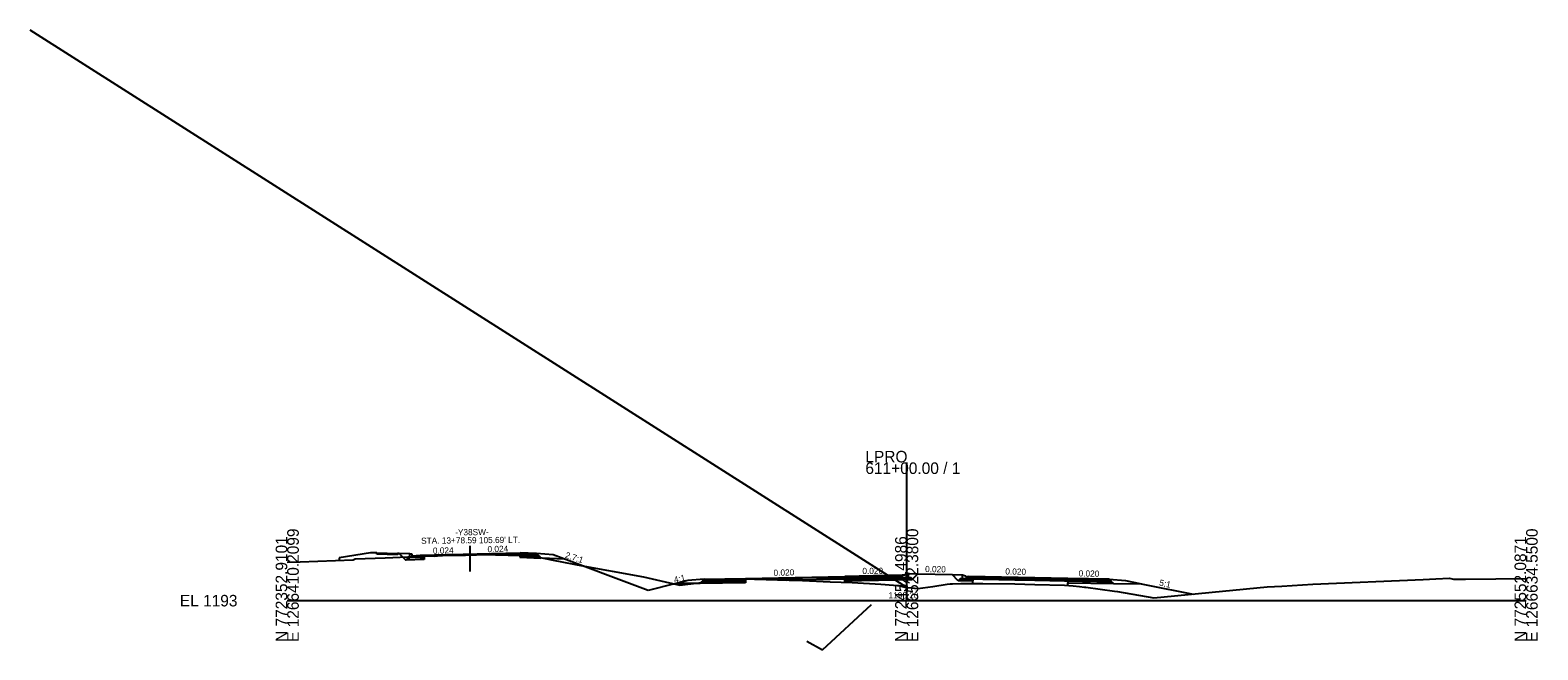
# Model space of a CAD drawing. Extents: x -3833 to 1267678, y -522 to 773248.
# Drawn here: x 1937.8 to 2302.8, y 1988.1 to 2138.3 of the extents above; entities that cross this region are included whole.
import ezdxf

# ---------------------------------------------------------------- set-up
doc = ezdxf.new("R2010")
doc.units = 0
for name, color, linetype in [('Exist Cross Section Cell', 7, 'Continuous'), ('Exist XS Center Line Elevation Label', 7, 'Continuous'), ('Exist XS Ground Line', 7, 'Continuous'), ('Prop CMT DNC', 7, 'Continuous'), ('Prop CMT Pvmt Course 1', 7, 'Continuous'), ('Prop CMT Pvmt Course 2', 7, 'Continuous'), ('Prop CMT Pvmt Course 3', 7, 'Continuous'), ('Prop CMT Pvmt Course 4', 7, 'Continuous'), ('Prop CMT Shld Paved Course 1', 7, 'Continuous'), ('Prop CMT Shld Paved Course 2', 7, 'Continuous'), ('Prop CMT Shld Paved Course 4', 7, 'Continuous'), ('Prop CMT Slope Fill', 7, 'Continuous'), ('Prop CMT Slope Grass', 7, 'Continuous'), ('Prop CMT Subgrade Earthwork', 7, 'Continuous'), ('Prop Conc 4in Sidewalk', 7, 'Continuous'), ('Prop Conc Curb and Gutter', 7, 'Continuous'), ('Prop Conc Island Cover', 7, 'Continuous'), ('Prop Corridor Mesh Bottom', 7, 'Continuous'), ('Prop XS Ditch Slope Text', 7, 'Continuous'), ('Prop XS Finish Grade', 7, 'Continuous'), ('Prop XS SE Text', 7, 'Continuous'), ('Prop XS Shear Point Element', 7, 'Continuous'), ('Prop XS Shear Point Label', 7, 'Continuous'), ('Scratch_Level_1', 7, 'Continuous'), ('Scratch_Level_5', 7, 'Continuous')]:
    doc.layers.add(name, color=color, linetype=linetype)

msp = doc.modelspace()

# ---------------------------------------------------------------- linework, layer by layer
at = {"layer": 'Exist Cross Section Cell'}
for p, q in [((2150, 2000), (2150, 2033.5)), ((2000, 2000), (2150, 2000)), ((2150, 2000), (2300, 2000))]:
    msp.add_line(p, q, dxfattribs=at)
at = {"layer": 'Exist XS Ground Line'}
for p, q in [((2000, 2009.3), (2003.1, 2009.4)), ((2003.1, 2009.4), (2015.97, 2009.92)), ((2015.97, 2009.92), (2016.47, 2010.11)), ((2016.47, 2010.11), (2023.71, 2010.36)), ((2023.71, 2010.36), (2029.18, 2010.6)), ((2029.18, 2010.6), (2037.57, 2010.91)), ((2037.57, 2010.91), (2041.57, 2011.02)), ((2041.57, 2011.02), (2043.16, 2011.06)), ((2043.16, 2011.06), (2044.63, 2011.1)), ((2044.63, 2011.1), (2045.84, 2011.13)), ((2045.84, 2011.13), (2047.34, 2011.17)), ((2047.34, 2011.17), (2056.54, 2010.98)), ((2056.54, 2010.98), (2058.68, 2010.94)), ((2058.68, 2010.94), (2061.64, 2010.35)), ((2061.64, 2010.35), (2064.77, 2009.72)), ((2064.77, 2009.72), (2066.12, 2009.46)), ((2066.12, 2009.46), (2070.19, 2008.72)), ((2070.19, 2008.72), (2086.27, 2005.78)), ((2086.27, 2005.78), (2091.54, 2004.53)), ((2091.54, 2004.53), (2095.06, 2003.75)), ((2099.06, 2004.26), (2104.76, 2004.93)), ((2104.76, 2004.93), (2106.62, 2005.16)), ((2106.62, 2005.16), (2107.61, 2005.27)), ((2107.61, 2005.27), (2109.06, 2005.26)), ((2109.06, 2005.26), (2113.22, 2005.24)), ((2113.22, 2005.24), (2121.55, 2004.98)), ((2121.55, 2004.98), (2124.8, 2004.88)), ((2124.8, 2004.88), (2131.44, 2004.6)), ((2131.44, 2004.6), (2136.83, 2004.39)), ((2136.83, 2004.39), (2143.74, 2003.97)), ((2248.36, 2003.97), (2275.09, 2005.13)), ((2275.09, 2005.13), (2278.17, 2005.26)), ((2278.17, 2005.26), (2281.47, 2005.43)), ((2281.47, 2005.43), (2282.42, 2005.19)), ((2282.42, 2005.19), (2285.33, 2005.22)), ((2285.33, 2005.22), (2300, 2005.38)), ((2095.06, 2003.75), (2099.06, 2004.26)), ((2143.74, 2003.97), (2146.81, 2003.79)), ((2146.81, 2003.79), (2147.75, 2003.71)), ((2147.75, 2003.71), (2148.12, 2003.68)), ((2148.12, 2003.68), (2149.61, 2003.24)), ((2149.61, 2003.24), (2150, 2003.2)), ((2150, 2003.2), (2151.12, 2003.09)), ((2151.12, 2003.09), (2152.67, 2002.94)), ((2152.67, 2002.94), (2156.36, 2003.42)), ((2156.36, 2003.42), (2159.79, 2003.98)), ((2159.79, 2003.98), (2160.57, 2004.06)), ((2160.57, 2004.06), (2161.11, 2004.1)), ((2161.11, 2004.1), (2163.11, 2004.15)), ((2163.11, 2004.15), (2164.19, 2004.16)), ((2164.19, 2004.16), (2168.46, 2004.14)), ((2168.46, 2004.14), (2176.23, 2004.1)), ((2176.23, 2004.1), (2181, 2003.95)), ((2181, 2003.95), (2188.25, 2003.73)), ((2188.25, 2003.73), (2190.31, 2003.56)), ((2190.31, 2003.56), (2191.82, 2003.45)), ((2191.82, 2003.45), (2193.04, 2003.29)), ((2193.04, 2003.29), (2193.39, 2003.24)), ((2193.39, 2003.24), (2200.33, 2002.31)), ((2200.33, 2002.31), (2201.07, 2002.18)), ((2201.07, 2002.18), (2209.89, 2000.65)), ((2209.89, 2000.65), (2237.32, 2003.35)), ((2237.32, 2003.35), (2240.81, 2003.51)), ((2240.81, 2003.51), (2248.36, 2003.97))]:
    msp.add_line(p, q, dxfattribs=at)
at = {"layer": 'Prop CMT Pvmt Course 1'}
for p, q in [((2029.2, 2010.33), (2029.68, 2010.34)), ((2032.18, 2011.01), (2056.37, 2011.59)), ((2032.18, 2010.76), (2036.4, 2010.86)), ((2032.18, 2010.43), (2033.18, 2010.45)), ((2048.22, 2011.15), (2056.37, 2011.34)), ((2055.79, 2011), (2056.36, 2011.01)), ((2111, 2005.38), (2135, 2005.86)), ((2135, 2005.61), (2111, 2005.25)), ((2111, 2005.25), (2111, 2005.38)), ((2111, 2005.38), (2111, 2005.38)), ((2135, 2005.86), (2135, 2005.86)), ((2135, 2005.86), (2135, 2005.86)), ((2135, 2005.86), (2135, 2005.61)), ((2135, 2005.61), (2135, 2005.61)), ((2189, 2005.38), (2165, 2005.86)), ((2165, 2005.86), (2165, 2005.86)), ((2165, 2005.86), (2165, 2005.86)), ((2165, 2005.86), (2165, 2005.61)), ((2165, 2005.61), (2165, 2005.61)), ((2189, 2005.13), (2189, 2005.38)), ((2189, 2005.38), (2189, 2005.38))]:
    msp.add_line(p, q, dxfattribs=at)
at = {"layer": 'Prop CMT Pvmt Course 2'}
for p, q in [((2148.91, 2005.89), (2135, 2005.61)), ((2135, 2005.61), (2135, 2005.61)), ((2135, 2005.61), (2135, 2005.28)), ((2135, 2005.28), (2148.91, 2005.56)), ((2135, 2005.28), (2135, 2005.28)), ((2150, 2005.58), (2150, 2005.58)), ((2150, 2005.58), (2150, 2005.58)), ((2165, 2005.28), (2165, 2005.61)), ((2165, 2005.61), (2165, 2005.61)), ((2165, 2005.28), (2165, 2005.28))]:
    msp.add_line(p, q, dxfattribs=at)
at = {"layer": 'Prop CMT Pvmt Course 3'}
for p, q in [((2148.92, 2005.56), (2148.91, 2005.56)), ((2150.92, 2005.6), (2148.92, 2005.56)), ((2151.21, 2005.31), (2150.92, 2005.6)), ((2162.7, 2005.03), (2162.99, 2005.32)), ((2166, 2005.84), (2166, 2004.77))]:
    msp.add_line(p, q, dxfattribs=at)
at = {"layer": 'Prop CMT Pvmt Course 4'}
for p, q in [((2028.7, 2009.85), (2029.2, 2010.33)), ((2028.7, 2009.85), (2028.7, 2009.85)), ((2028.7, 2009.85), (2028.7, 2009.85)), ((2032.18, 2009.97), (2032.18, 2009.97)), ((2135, 2005.28), (2148.91, 2005.56)), ((2135, 2004.46), (2135, 2005.28)), ((2135, 2005.28), (2135, 2005.28)), ((2135, 2005.28), (2135, 2005.28)), ((2135, 2004.82), (2151.37, 2005.15)), ((2150, 2005.58), (2150, 2005.58)), ((2150, 2005.58), (2150, 2005.58)), ((2150.42, 2005.59), (2150.92, 2005.6)), ((2150.92, 2005.6), (2151.37, 2005.15)), ((2162.99, 2005.32), (2162.51, 2004.84)), ((2163.49, 2005.31), (2162.99, 2005.32)), ((2165, 2005.28), (2165, 2005.28)), ((2165, 2005.28), (2165, 2005.28))]:
    msp.add_line(p, q, dxfattribs=at)
at = {"layer": 'Prop CMT Shld Paved Course 1'}
for p, q in [((2032.18, 2010.43), (2032.18, 2010.43)), ((2035.66, 2011), (2035.66, 2011)), ((2035.66, 2010.52), (2035.66, 2010.52)), ((2041.45, 2011.2), (2041.45, 2011.2)), ((2041.45, 2010.9), (2041.45, 2010.9)), ((2044.3, 2011.3), (2044.3, 2011.3)), ((2044.3, 2011.06), (2044.3, 2011.06)), ((2044.3, 2011.06), (2044.3, 2011.06)), ((2044.3, 2011.06), (2044.3, 2011.06)), ((2044.63, 2011.32), (2044.63, 2011.32)), ((2044.63, 2011.07), (2044.63, 2011.07)), ((2045.05, 2011.1), (2045.05, 2011.1)), ((2045.06, 2011.33), (2045.06, 2011.33)), ((2047.64, 2011.42), (2047.64, 2011.42)), ((2047.64, 2011.19), (2047.64, 2011.19)), ((2047.87, 2011.2), (2047.87, 2011.2)), ((2047.87, 2011.2), (2047.87, 2011.2)), ((2047.88, 2011.43), (2047.88, 2011.43)), ((2047.88, 2011.43), (2047.88, 2011.43)), ((2050.06, 2011.51), (2050.06, 2011.51)), ((2050.06, 2011.21), (2050.06, 2011.21)), ((2056.37, 2011.59), (2056.36, 2011.09)), ((2056.36, 2011.09), (2056.36, 2011.09)), ((2060.37, 2011.41), (2056.37, 2011.59)), ((2056.37, 2011.59), (2056.37, 2011.34)), ((2056.37, 2011.34), (2056.37, 2011.34)), ((2056.37, 2011.34), (2060.63, 2011.15)), ((2060.63, 2011.15), (2060.37, 2011.41)), ((2060.37, 2011.41), (2060.37, 2011.41)), ((2060.63, 2011.15), (2060.63, 2011.15)), ((2060.63, 2011.15), (2060.63, 2011.15)), ((2100.74, 2004.93), (2101, 2005.18)), ((2111, 2005.13), (2100.74, 2004.93)), ((2101, 2005.18), (2111, 2005.38)), ((2111, 2005.38), (2111, 2005.13)), ((2148.91, 2006.14), (2135, 2005.86)), ((2135, 2005.61), (2148.91, 2005.89)), ((2135, 2005.86), (2135, 2005.86)), ((2135, 2005.86), (2135, 2005.61)), ((2150, 2006.16), (2150, 2006.16)), ((2150, 2006.16), (2150, 2006.16)), ((2150, 2005.91), (2150, 2005.91)), ((2165, 2005.61), (2165, 2005.86)), ((2165, 2005.86), (2165, 2005.86)), ((2189, 2005.38), (2189, 2005.13)), ((2199, 2005.18), (2189, 2005.38)), ((2189, 2005.13), (2199.26, 2004.93)), ((2199.26, 2004.93), (2199, 2005.18))]:
    msp.add_line(p, q, dxfattribs=at)
at = {"layer": 'Prop CMT Shld Paved Course 2'}
for p, q in [((2032.18, 2010.43), (2032.18, 2010.43)), ((2033.18, 2010.46), (2033.18, 2010.46)), ((2033.18, 2010.46), (2033.18, 2010.46)), ((2056.37, 2011.34), (2056.36, 2011.01)), ((2056.36, 2011.01), (2056.36, 2011.01)), ((2056.36, 2011.01), (2060.97, 2010.8)), ((2060.63, 2011.15), (2056.37, 2011.34)), ((2060.97, 2010.8), (2060.63, 2011.15)), ((2060.63, 2011.15), (2060.63, 2011.15)), ((2060.97, 2010.8), (2060.97, 2010.8)), ((2060.97, 2010.8), (2060.97, 2010.8)), ((2100.41, 2004.59), (2100.74, 2004.93)), ((2111, 2004.8), (2100.41, 2004.59)), ((2100.74, 2004.93), (2111, 2005.13)), ((2111, 2005.13), (2111, 2004.8)), ((2111.01, 2005.25), (2113.17, 2005.24)), ((2113.17, 2005.24), (2111.01, 2005.25)), ((2113.17, 2005.24), (2113.23, 2005.24)), ((2113.3, 2005.24), (2113.17, 2005.24)), ((2113.23, 2005.24), (2113.3, 2005.24)), ((2121.55, 2005.34), (2113.3, 2005.24)), ((2113.3, 2005.24), (2114.43, 2005.2)), ((2114.43, 2005.2), (2114.43, 2005.2)), ((2114.43, 2005.2), (2120.94, 2005)), ((2120.94, 2005), (2121.55, 2005.01)), ((2120.94, 2005), (2120.94, 2005)), ((2124.8, 2005.41), (2121.55, 2005.34)), ((2121.55, 2005.34), (2121.55, 2005.34)), ((2121.55, 2005.01), (2124.8, 2005.07)), ((2121.55, 2005.01), (2121.55, 2005.01)), ((2131.44, 2005.54), (2124.8, 2005.41)), ((2124.8, 2005.07), (2131.44, 2005.21)), ((2135, 2005.61), (2131.44, 2005.54)), ((2131.44, 2005.54), (2131.44, 2005.54)), ((2131.44, 2005.21), (2135, 2005.28)), ((2131.44, 2005.21), (2131.44, 2005.21)), ((2135, 2005.28), (2135, 2005.61)), ((2135, 2005.61), (2135, 2005.61)), ((2135, 2005.61), (2135, 2005.61)), ((2135, 2005.28), (2135, 2005.28)), ((2168.46, 2005.54), (2165, 2005.61)), ((2165, 2005.61), (2165, 2005.61)), ((2165, 2005.61), (2165, 2005.28)), ((2165, 2005.28), (2168.46, 2005.21)), ((2176.23, 2005.39), (2168.46, 2005.54)), ((2168.46, 2005.54), (2168.46, 2005.54)), ((2168.46, 2005.21), (2168.46, 2005.21)), ((2168.46, 2005.21), (2176.23, 2005.05)), ((2181, 2005.29), (2176.23, 2005.39)), ((2176.23, 2005.39), (2176.23, 2005.39)), ((2176.23, 2005.05), (2176.23, 2005.05)), ((2176.23, 2005.05), (2181, 2004.96)), ((2188.25, 2005.15), (2181, 2005.29)), ((2181, 2005.29), (2181, 2005.29)), ((2181, 2004.96), (2181, 2004.96)), ((2181, 2004.96), (2188.25, 2004.81)), ((2188.25, 2005.15), (2188.25, 2005.15)), ((2189, 2005.13), (2188.25, 2005.15)), ((2188.25, 2005.15), (2188.25, 2005.15)), ((2188.25, 2004.81), (2188.25, 2004.81)), ((2188.25, 2004.81), (2188.25, 2004.81)), ((2188.25, 2004.81), (2189, 2004.8)), ((2189, 2004.8), (2189, 2005.13)), ((2189, 2005.13), (2189, 2005.13)), ((2189, 2005.13), (2189, 2004.8)), ((2199.26, 2004.93), (2189, 2005.13)), ((2189, 2004.8), (2199.59, 2004.59)), ((2199.59, 2004.59), (2199.26, 2004.93))]:
    msp.add_line(p, q, dxfattribs=at)
at = {"layer": 'Prop CMT Shld Paved Course 4'}
for p, q in [((2032.18, 2009.97), (2032.18, 2009.97)), ((2033.18, 2010.46), (2033.18, 2010.46)), ((2033.18, 2010.01), (2033.18, 2010.01)), ((2033.18, 2010.01), (2033.18, 2010.01)), ((2056.36, 2011.01), (2056.35, 2010.55)), ((2056.35, 2010.55), (2056.35, 2010.55)), ((2056.35, 2010.55), (2061.44, 2010.32)), ((2060.47, 2010.83), (2056.36, 2011.01)), ((2060.97, 2010.8), (2060.47, 2010.83)), ((2060.47, 2010.83), (2060.47, 2010.83)), ((2061.44, 2010.32), (2060.97, 2010.8)), ((2060.97, 2010.8), (2060.97, 2010.8)), ((2061.44, 2010.32), (2061.44, 2010.32)), ((2061.44, 2010.32), (2061.44, 2010.32)), ((2099.94, 2004.12), (2100.41, 2004.59)), ((2111, 2004.34), (2099.94, 2004.12)), ((2100.41, 2004.59), (2100.91, 2004.6)), ((2100.91, 2004.6), (2111, 2004.8)), ((2111, 2004.8), (2111, 2004.34)), ((2189, 2004.8), (2189, 2004.34)), ((2199.09, 2004.6), (2189, 2004.8)), ((2189, 2004.34), (2200.06, 2004.12)), ((2199.59, 2004.59), (2199.09, 2004.6)), ((2200.06, 2004.12), (2199.59, 2004.59))]:
    msp.add_line(p, q, dxfattribs=at)
at = {"layer": 'Prop CMT Slope Grass'}
for p, q in [((2029.68, 2011.37), (2027.1, 2011.43)), ((2064.37, 2011.07), (2060.37, 2011.41)), ((2101, 2005.18), (2097, 2004.86)), ((2150.42, 2006.57), (2150.72, 2006.56)), ((2150.72, 2006.56), (2152.74, 2006.52)), ((2161.01, 2006.34), (2163.49, 2006.29)), ((2199, 2005.18), (2203, 2004.86)), ((2203, 2004.86), (2206.78, 2004.1))]:
    msp.add_line(p, q, dxfattribs=at)
at = {"layer": 'Prop CMT Subgrade Earthwork'}
for p, q in [((2027.1, 2011.43), (2028.7, 2009.85)), ((2033.18, 2010.01), (2028.7, 2009.85)), ((2033.18, 2010.75), (2033.18, 2010.01)), ((2056.36, 2010.98), (2056.35, 2010.55)), ((2067.05, 2010.07), (2056.35, 2010.55)), ((2111, 2004.34), (2099.94, 2004.12)), ((2111, 2005.25), (2111, 2004.34)), ((2151.37, 2005.15), (2135, 2004.82)), ((2135, 2004.82), (2135, 2004.46)), ((2151.37, 2005.15), (2152.74, 2006.52)), ((2162.51, 2004.84), (2161.01, 2006.34)), ((2166, 2004.77), (2162.51, 2004.84)), ((2166, 2004.15), (2166, 2004.77)), ((2189, 2003.66), (2189, 2004.34)), ((2189, 2004.34), (2200.06, 2004.12)), ((2099.94, 2004.12), (2094.3, 2004.19)), ((2200.06, 2004.12), (2206.78, 2004.1))]:
    msp.add_line(p, q, dxfattribs=at)
at = {"layer": 'Prop Conc 4in Sidewalk'}
for p, q in [((2021.67, 2011.23), (2021.68, 2011.57)), ((2026.69, 2011.11), (2021.67, 2011.23)), ((2021.68, 2011.57), (2026.68, 2011.44)), ((2026.68, 2011.44), (2026.69, 2011.11))]:
    msp.add_line(p, q, dxfattribs=at)
at = {"layer": 'Prop Conc Curb and Gutter'}
for p, q in [((2029.68, 2010.34), (2029.68, 2011.37)), ((2029.68, 2011.37), (2029.68, 2011.37)), ((2029.68, 2011.37), (2030.18, 2011.36)), ((2032.18, 2010.43), (2029.68, 2010.34)), ((2029.68, 2010.34), (2029.68, 2010.34)), ((2029.68, 2010.34), (2029.68, 2010.34)), ((2030.18, 2011.36), (2030.18, 2010.86)), ((2030.18, 2010.86), (2032.18, 2011.01)), ((2030.18, 2010.86), (2030.18, 2010.86)), ((2030.18, 2010.86), (2030.18, 2010.86)), ((2032.18, 2011.01), (2032.18, 2010.43)), ((2032.18, 2010.43), (2032.18, 2010.43)), ((2148.91, 2006.14), (2148.91, 2006.14)), ((2148.91, 2006.14), (2148.91, 2005.56)), ((2148.92, 2006.14), (2148.91, 2006.14)), ((2148.91, 2005.56), (2148.92, 2005.56)), ((2149.66, 2006.15), (2148.92, 2006.14)), ((2148.92, 2005.56), (2150.42, 2005.59)), ((2150.42, 2006.57), (2149.66, 2006.32)), ((2149.66, 2006.32), (2149.66, 2006.32)), ((2149.66, 2006.32), (2149.66, 2006.15)), ((2149.66, 2006.15), (2149.66, 2006.15)), ((2150.42, 2005.59), (2150.42, 2006.57)), ((2150.42, 2005.59), (2150.42, 2005.59)), ((2163.49, 2005.31), (2163.49, 2006.29)), ((2163.49, 2006.29), (2163.49, 2006.29)), ((2163.49, 2006.29), (2163.49, 2006.29)), ((2163.49, 2006.29), (2164.25, 2006.04)), ((2165, 2005.28), (2163.49, 2005.31)), ((2163.49, 2005.31), (2163.49, 2005.31)), ((2164.25, 2006.04), (2164.25, 2006.04)), ((2164.25, 2006.04), (2164.25, 2005.87)), ((2164.25, 2005.87), (2165, 2005.86)), ((2164.25, 2005.87), (2164.25, 2005.87)), ((2165, 2005.86), (2165, 2005.86)), ((2165, 2005.86), (2165, 2005.28))]:
    msp.add_line(p, q, dxfattribs=at)
at = {"layer": 'Prop Conc Island Cover'}
for p, q in [((2163.49, 2006.29), (2163.49, 2006.29)), ((2163.49, 2006.29), (2163.49, 2006.29)), ((2163.49, 2006.04), (2163.49, 2006.04)), ((2163.49, 2006.04), (2163.49, 2006.04))]:
    msp.add_line(p, q, dxfattribs=at)
at = {"layer": 'Prop Corridor Mesh Bottom'}
for p, q in [((2111, 2005.38), (2111, 2005.13)), ((2135, 2005.86), (2135, 2005.61)), ((2165, 2005.86), (2165, 2005.61)), ((2189, 2005.38), (2189, 2005.13))]:
    msp.add_line(p, q, dxfattribs=at)
at = {"layer": 'Prop XS Finish Grade'}
for p, q in [((2020.18, 2011.6), (2012.61, 2010.36)), ((2012.61, 2010.36), (2012.61, 2009.79)), ((2021.68, 2011.57), (2020.18, 2011.6)), ((2021.68, 2011.57), (2026.68, 2011.44)), ((2027.1, 2011.43), (2026.68, 2011.44)), ((2087.42, 2002.46), (2064.37, 2011.07)), ((2097, 2004.86), (2093.74, 2004.04)), ((2152.74, 2006.52), (2161.01, 2006.34)), ((2163.49, 2006.29), (2163.49, 2006.29)), ((2093.74, 2004.04), (2087.42, 2002.46))]:
    msp.add_line(p, q, dxfattribs=at)
msp.add_lwpolyline([(2203, 2004.86), (2208, 2003.86), (2219.39, 2001.58)], dxfattribs=at)
at = {"layer": 'Prop XS Shear Point Element'}
msp.add_line((2044.3, 2007.03), (2044.3, 2013.3), dxfattribs=at)
at = {"layer": 'Prop XS Shear Point Label'}
msp.add_line((2044.3, 2011.3), (2044.3, 2011.3), dxfattribs=at)
at = {"layer": 'Scratch_Level_1'}
msp.add_line((2150, 2003.2), (1937.75, 2138.26), dxfattribs=at)
at = {"layer": 'Scratch_Level_5'}
for p, q in [((2129.62, 1988.07), (2141.48, 1999.1)), ((2125.84, 1990.18), (2129.62, 1988.07))]:
    msp.add_line(p, q, dxfattribs=at)

# ---------------------------------------------------------------- texts
at = {"layer": 'Exist Cross Section Cell'}
for s, p in [('611+00.00 / 1', (2140, 2030.7)), ('LPRO', (2140, 2033.5)), ('EL 1193', (1974, 1998.6))]:
    msp.add_text(s, height=2.8, dxfattribs=at).set_placement(p)
for s, p in [('N 772352.9101', (2000, 1990)), ('E 1266410.2099', (2002.8, 1990)), ('N 772452.4986', (2150, 1990)), ('E 1266522.3800', (2152.8, 1990)), ('N 772552.0871', (2300, 1990)), ('E 1266634.5500', (2302.8, 1990))]:
    msp.add_text(s, height=2.8, rotation=90, dxfattribs=at).set_placement(p)
at = {"layer": 'Exist XS Center Line Elevation Label'}
msp.add_text('1196.20', height=1.5, dxfattribs=at).set_placement((2145.6, 2000.53))
at = {"layer": 'Prop CMT DNC'}
for p in [(2111, 2005.38), (2111, 2005.38), (2135, 2005.86), (2135, 2005.86), (2149.66, 2006.15), (2150, 2006.16), (2164.25, 2005.87), (2165, 2005.86), (2165, 2005.86), (2189, 2005.38), (2189, 2005.38), (2199, 2005.18)]:
    msp.add_text('X', height=0.00025, dxfattribs=at).set_placement(p)
at = {"layer": 'Prop CMT Slope Fill'}
for p in [(2030.3, 2010.87), (2032.3, 2011.02), (2032.3, 2011.02), (2064.26, 2011.07)]:
    msp.add_text('X', height=0.00025, rotation=359.7139, dxfattribs=at).set_placement(p)
at = {"layer": 'Prop CMT Slope Grass'}
msp.add_text('X', height=0.00025, rotation=359.7139, dxfattribs=at).set_placement((2062.46, 2011.22))
at = {"layer": 'Prop XS Ditch Slope Text'}
for s, rotation, p in [('2.7:1', 342.0153, (2067.18, 2010.42)), ('4:1', 13.1107, (2093.81, 2004.29)), ('5:1', 347.5411, (2211.06, 2003.69))]:
    msp.add_text(s, height=1.5, rotation=rotation, dxfattribs=at).set_placement(p)
at = {"layer": 'Prop XS SE Text'}
for s, rotation, p in [("STA. 13+78.59 105.69' LT.", 0.5826, (2032.43, 2013.77)), ('-Y38SW-', 0.5826, (2040.67, 2015.81)), ('0.024', 1.397, (2035.29, 2011.35)), ('0.024', 1.397, (2048.51, 2011.72)), ('0.020', 0.2693, (2139.28, 2006.45)), ('0.020', 358.8542, (2154.45, 2006.93)), ('0.020', 1.397, (2117.78, 2006.01)), ('0.020', 358.8542, (2173.88, 2006.34)), ('0.020', 358.8542, (2191.62, 2005.88))]:
    msp.add_text(s, height=1.5, rotation=rotation, dxfattribs=at).set_placement(p)

doc.saveas('drawing.dxf')
